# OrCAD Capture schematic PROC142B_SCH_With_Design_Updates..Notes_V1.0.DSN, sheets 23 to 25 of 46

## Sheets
23 22. OSPI INTERFACE: size C; title: SOC OSPI/QSPI INTERFACE AND OSPI FLASH
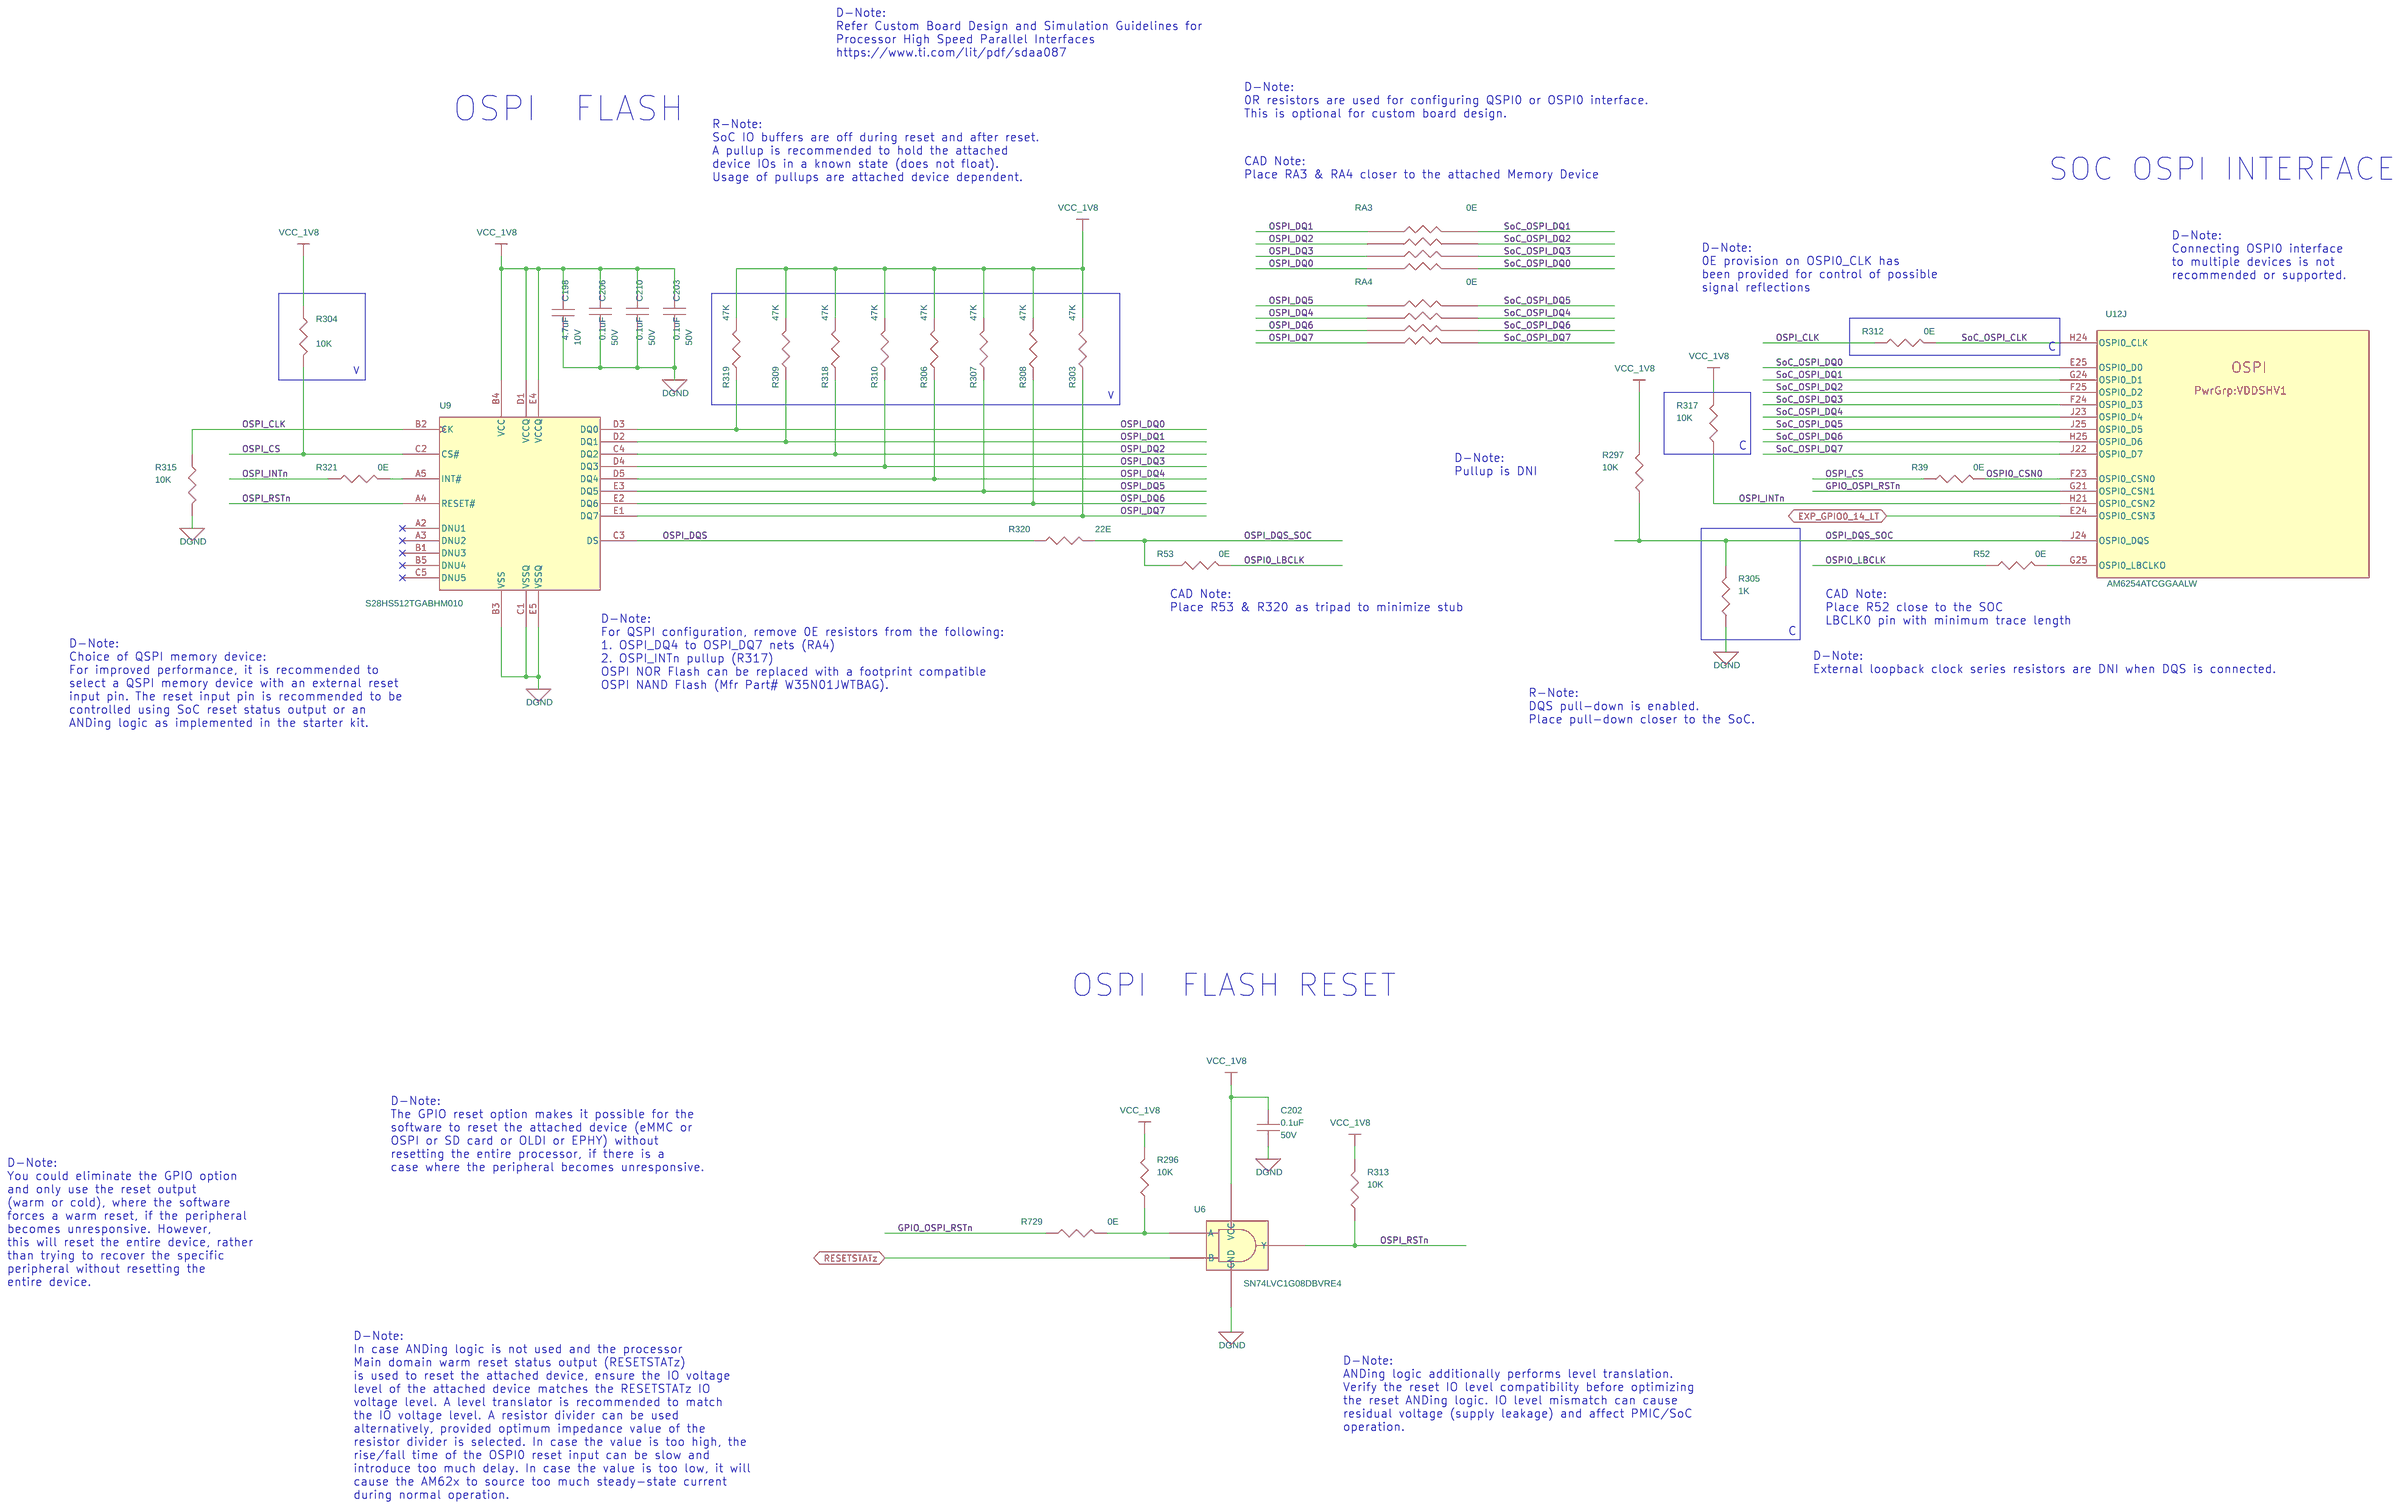
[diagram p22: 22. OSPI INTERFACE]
24 23. BRD ID EEPROM &TEMP SENSORS: size C; title: BOARD ID EEPROM & DIGITAL TEMPERATURE SENSORS
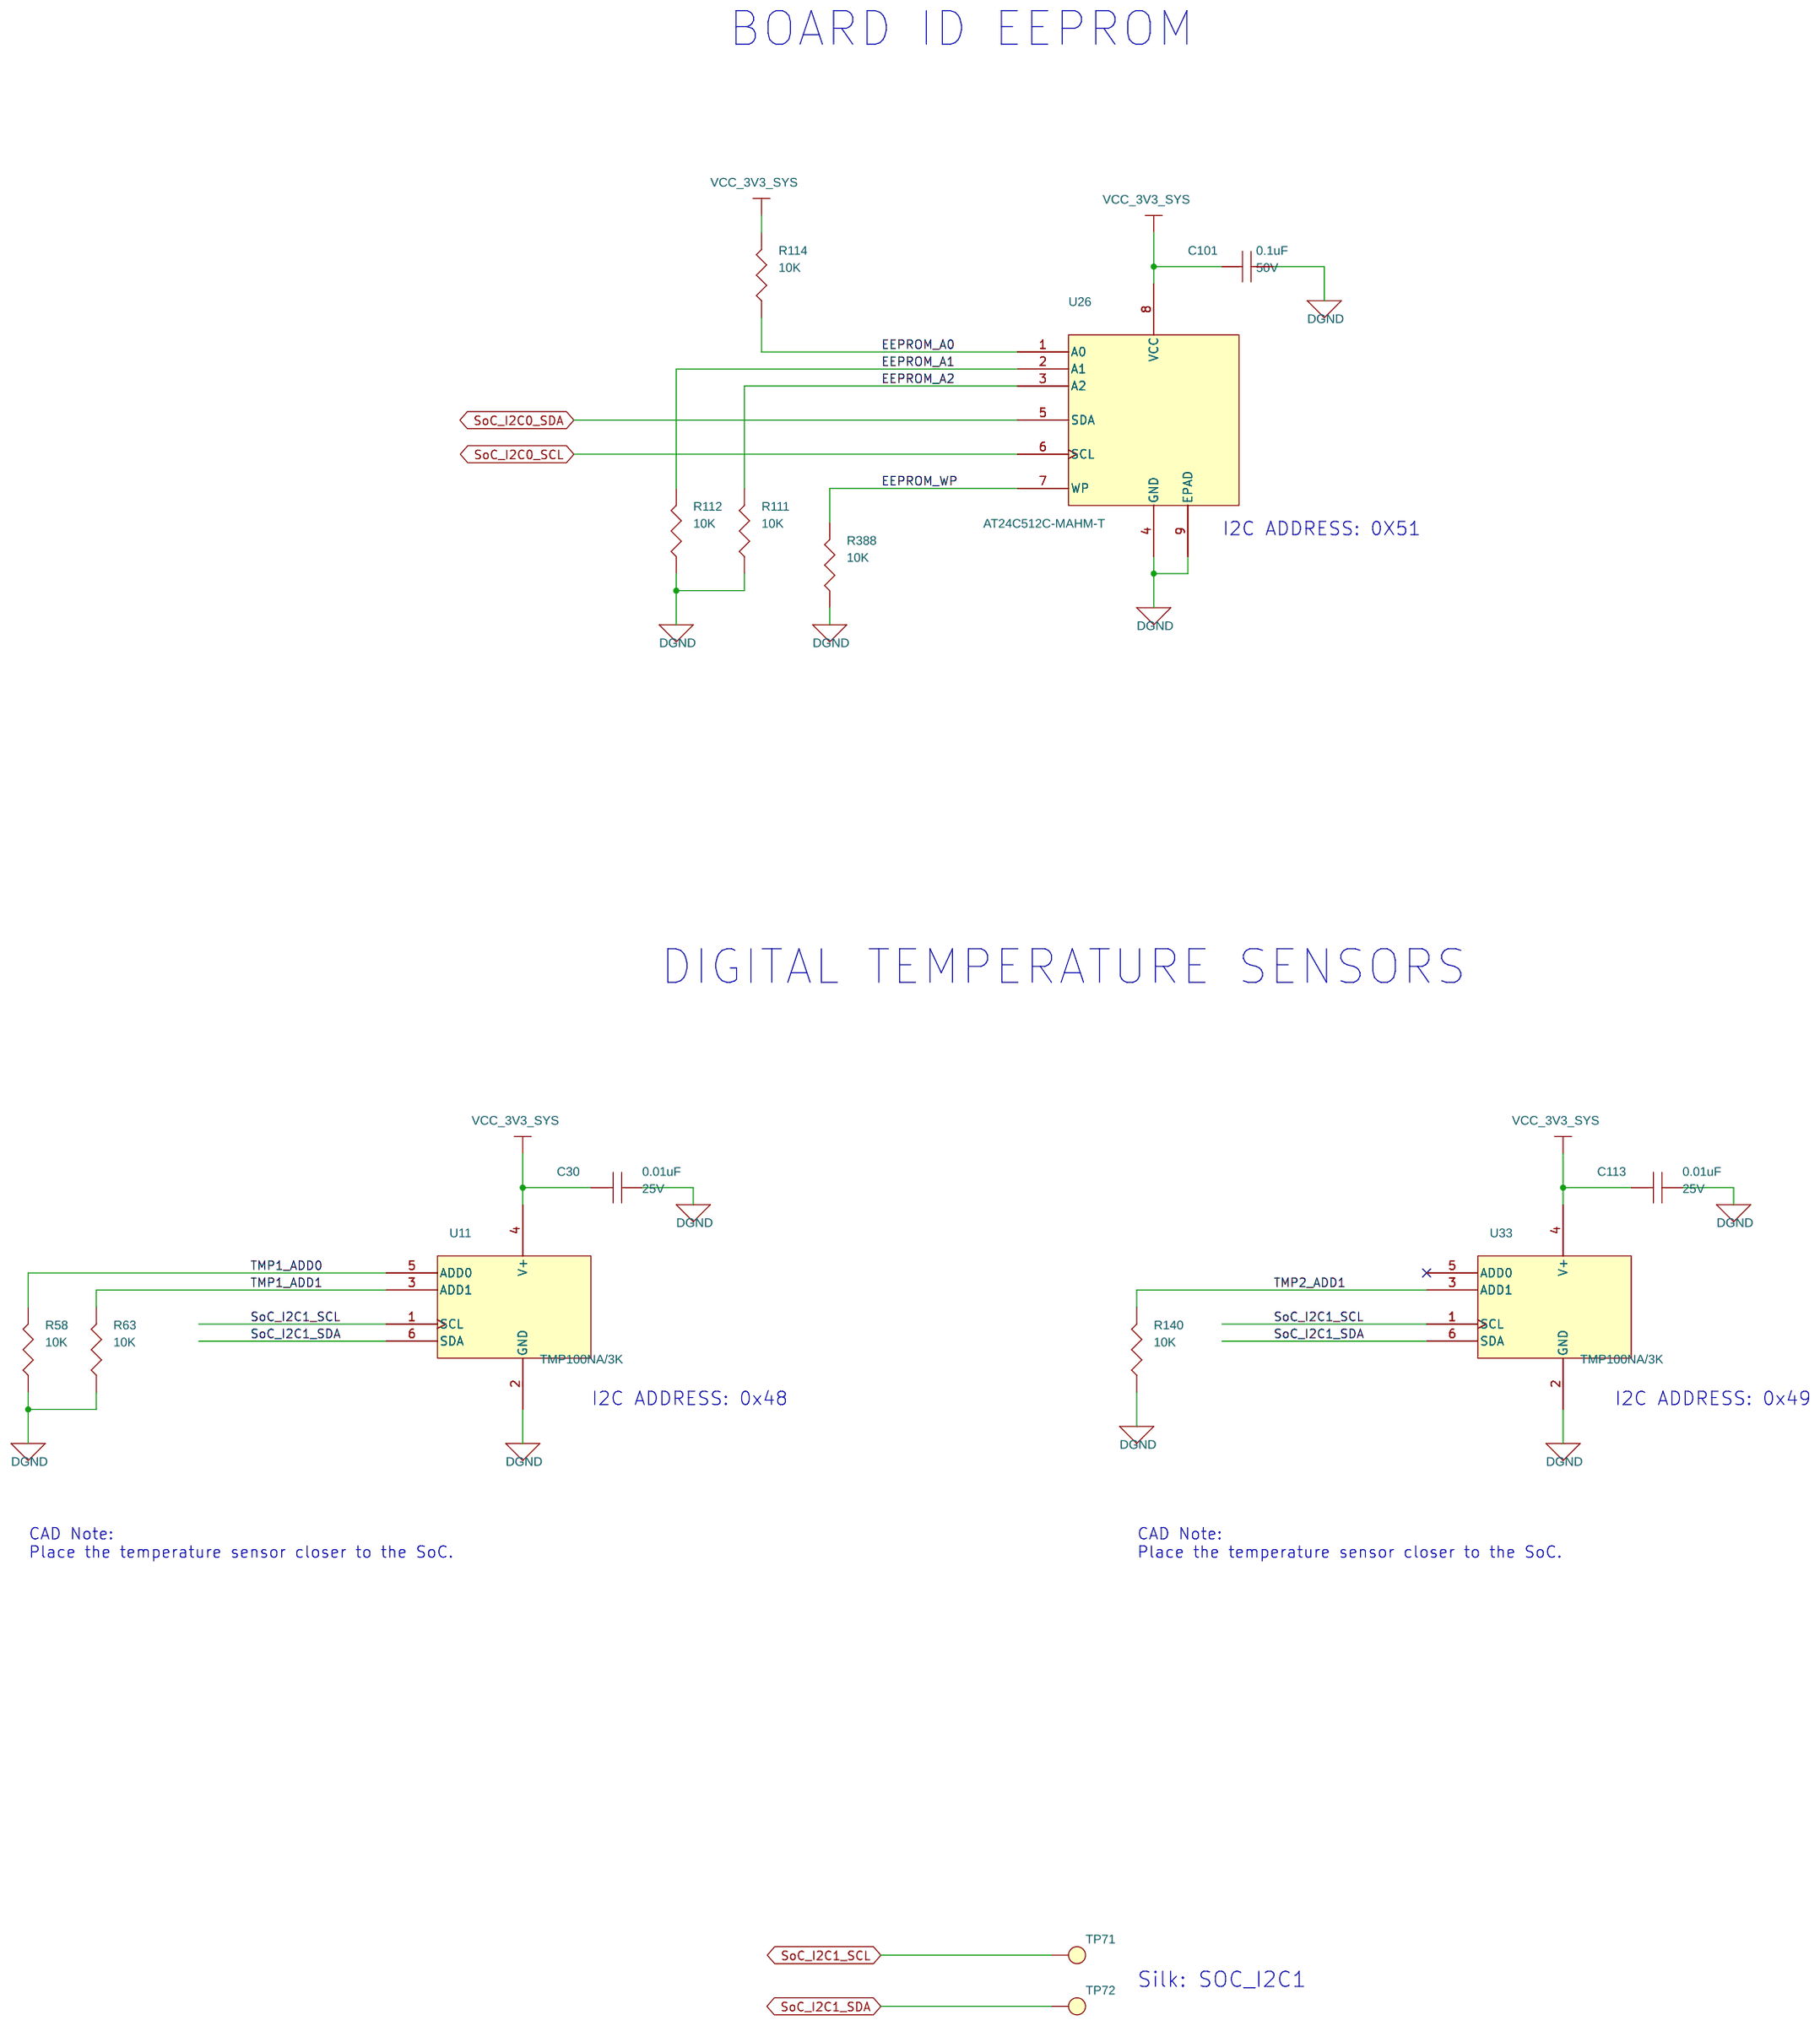
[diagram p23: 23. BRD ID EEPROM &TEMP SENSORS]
25 24. CPSW RGMII_1 ETHERNET PHY: size C; title: CPSW3G RGMII_1 ETHERNET PHY
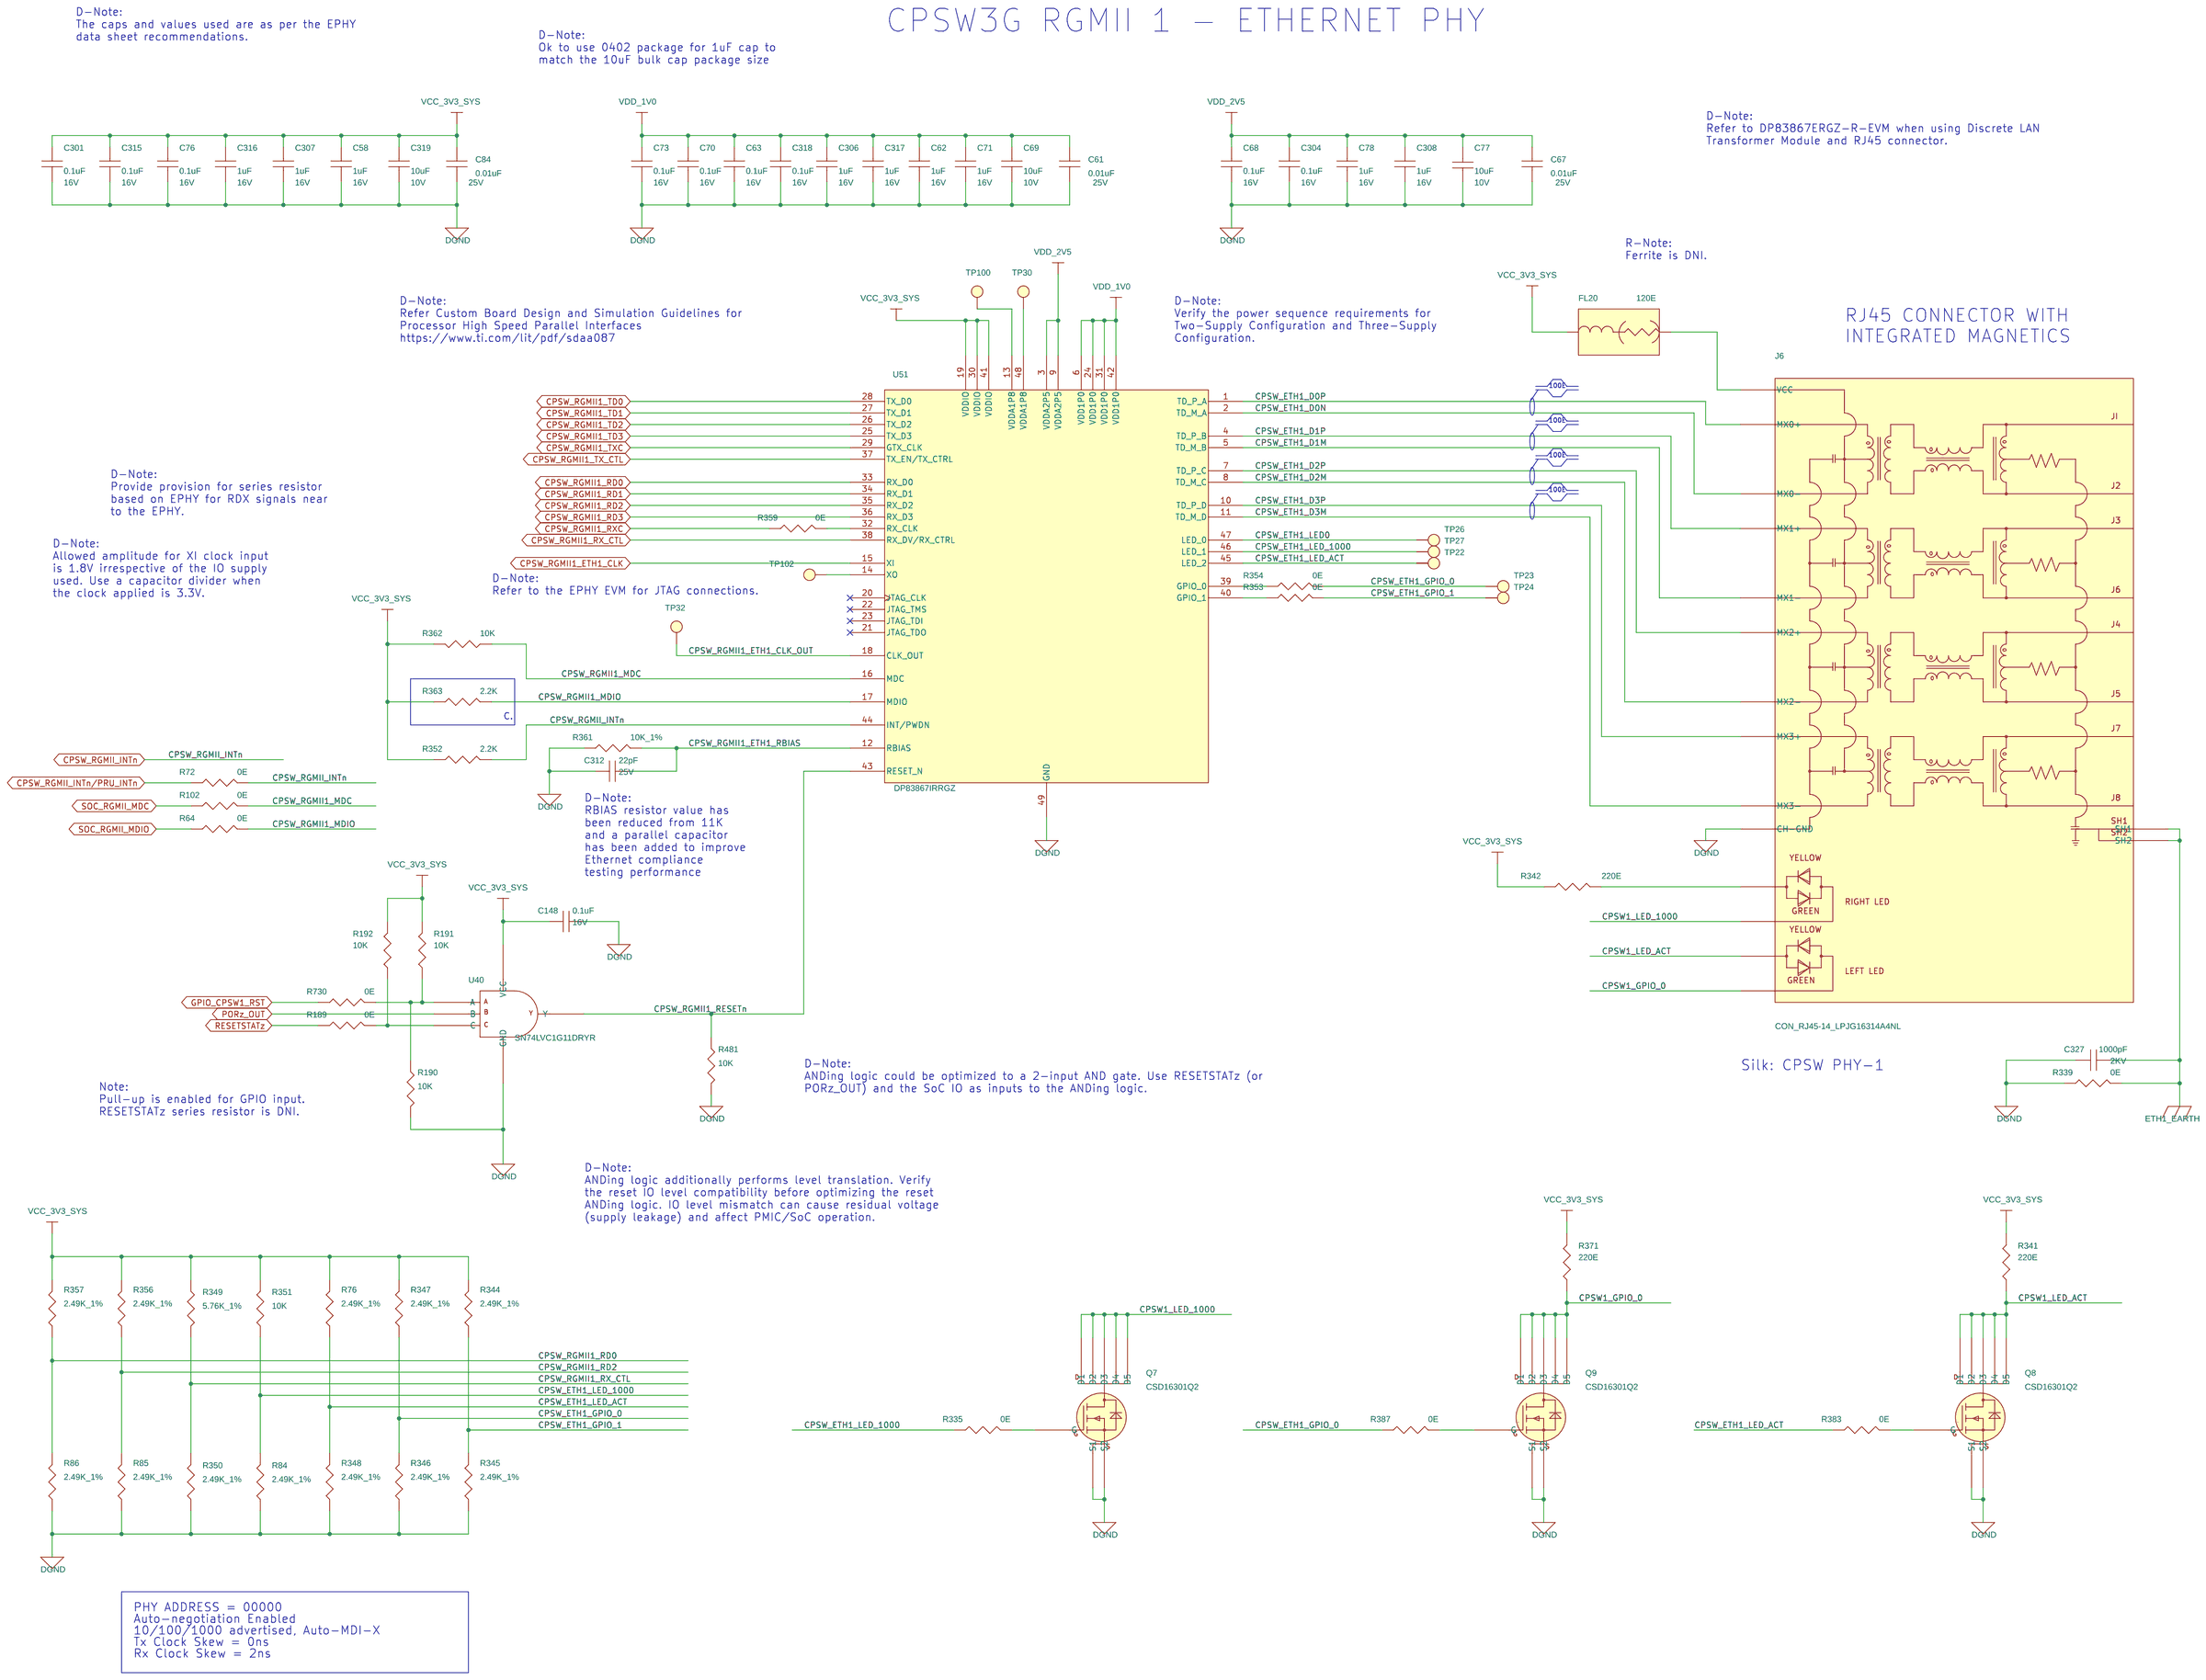
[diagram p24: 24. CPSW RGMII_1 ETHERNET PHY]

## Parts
sheet 22. OSPI INTERFACE
C198  4.7uF  [CAP0402_0-75]
C202  0.1uF  [CAP0402_0-75]
C203  0.1uF  [CAP0402_0-75]
C206  0.1uF  [CAP0402_0-75]
C210  0.1uF  [CAP0402_0-75]
R39  0E  [RES0201_0-5]
R52  0E  [RES0201_0-5]
R53  0E  [RES0402_0-5]
R296  10K  [RES0201_0-5]
R297  10K  [RES0201_0-5]
R303  47K  [RES0201_0-5]
R304  10K  [RES0402_0-5]
R305  1K  [RES0402_0-5]
R306  47K  [RES0201_0-5]
R307  47K  [RES0201_0-5]
R308  47K  [RES0201_0-5]
R309  47K  [RES0201_0-5]
R310  47K  [RES0201_0-5]
R312  0E  [RES0402_0-5]
R313  10K  [RES0201_0-5]
R315  10K  [RES0201_0-5]
R317  10K  [RES0201_0-5]
R318  47K  [RES0201_0-5]
R319  47K  [RES0201_0-5]
R320  22E  [RES0402_0-5]
R321  0E  [RES0402_0-5]
R729  0E  [RES0402_0-5]
RA3  0E  [RESA_EXB_0201-4_0-5]
RA4  0E  [RESA_EXB_0201-4_0-5]
U6  SN74LVC1G08DBVRE4  [SOT23-5]
U9  S28HS512TGABHM010  [BGA24_39-37_240X310_1]
sheet 23. BRD ID EEPROM &TEMP SENSORS
C30  0.01uF  [CAP0201_0-5]
C101  0.1uF  [CAP0402_0-75]
C113  0.01uF  [CAP0201_0-5]
R58  10K  [RES0201_0-5]
R63  10K  [RES0201_0-5]
R111  10K  [RES0201_0-5]
R112  10K  [RES0201_0-5]
R114  10K  [RES0201_0-5]
R140  10K  [RES0201_0-5]
R388  10K  [RES0201_0-5]
TP71  THRU HOLE  [TP_36X22]
TP72  THRU HOLE  [TP_36X22]
U11  TMP100NA/3K  [SOT23-6_1-5]
U26  AT24C512C-MAHM-T  [UDFN8_19-68_120X80_0-6]
U33  TMP100NA/3K  [SOT23-6_1-5]
sheet 24. CPSW RGMII_1 ETHERNET PHY
C58  1uF  [CAP0201_0-5]
C61  0.01uF  [CAP0201_0-5]
C62  1uF  [CAP0201_0-5]
C63  0.1uF  [CAP0201_0-5]
C67  0.01uF  [CAP0201_0-5]
C68  0.1uF  [CAP0201_0-5]
C69  10uF  [CAP0402_0-75]
C70  0.1uF  [CAP0201_0-5]
C71  1uF  [CAP0201_0-5]
C73  0.1uF  [CAP0201_0-5]
C76  0.1uF  [CAP0201_0-5]
C77  10uF  [CAP0402_0-75]
C78  1uF  [CAP0201_0-5]
C84  0.01uF  [CAP0201_0-5]
C148  0.1uF  [CAP0201_0-5]
C301  0.1uF  [CAP0201_0-5]
C304  0.1uF  [CAP0201_0-5]
C306  1uF  [CAP0201_0-5]
C307  1uF  [CAP0201_0-5]
C308  1uF  [CAP0201_0-5]
C312  22pF  [CAP0201_0-5]
C315  0.1uF  [CAP0201_0-5]
C316  1uF  [CAP0201_0-5]
C317  1uF  [CAP0201_0-5]
C318  0.1uF  [CAP0201_0-5]
C319  10uF  [CAP0402_0-75]
C327  1000pF  [CAP1206_1-75]
FL20  120E  [EMIFIL_BLM15P_0402]
J6  CON_RJ45-14_LPJG16314A4NL  [CON_RJ45-14_LPJG16314A4NL_S_R_T_13-6]
Q7  CSD16301Q2  [WSON6_CSD13202Q2_80X80_0-8]
Q8  CSD16301Q2  [WSON6_CSD13202Q2_80X80_0-8]
Q9  CSD16301Q2  [WSON6_CSD13202Q2_80X80_0-8]
R64  0E  [RES0402_0-5]
R72  0E  [RES0402_0-5]
R76  2.49K_1%  [RES0402_0-5]
R84  2.49K_1%  [RES0402_0-5]
R85  2.49K_1%  [RES0402_0-5]
R86  2.49K_1%  [RES0402_0-5]
R102  0E  [RES0402_0-5]
R189  0E  [RES0402_0-5]
R190  10K  [RES0201_0-5]
R191  10K  [RES0201_0-5]
R192  10K  [RES0201_0-5]
R335  0E  [RES0402_0-5]
R339  0E  [RES0603_0-75]
R341  220E  [RES0402_0-5]
R342  220E  [RES0402_0-5]
R344  2.49K_1%  [RES0402_0-5]
R345  2.49K_1%  [RES0402_0-5]
R346  2.49K_1%  [RES0402_0-5]
R347  2.49K_1%  [RES0402_0-5]
R348  2.49K_1%  [RES0402_0-5]
R349  5.76K_1%  [RES0402_0-5]
R350  2.49K_1%  [RES0402_0-5]
R351  10K  [RES0201_0-5]
R352  2.2K  [RES0402_0-5]
R353  0E  [RES0201_0-5]
R354  0E  [RES0201_0-5]
R356  2.49K_1%  [RES0402_0-5]
R357  2.49K_1%  [RES0402_0-5]
R359  0E  [RES0402_0-5]
R361  10K_1%  [RES0201_0-5]
R362  10K  [RES0201_0-5]
R363  2.2K  [RES0201_0-5]
R371  220E  [RES0402_0-5]
R383  0E  [RES0402_0-5]
R387  0E  [RES0402_0-5]
R481  10K  [RES0201_0-5]
R730  0E  [RES0402_0-5]
TP22  TP20_SMD  [TP20_SMD]
TP23  TP20_SMD  [TP20_SMD]
TP24  TP20_SMD  [TP20_SMD]
TP26  TP20_SMD  [TP20_SMD]
TP27  TP20_SMD  [TP20_SMD]
TP30  TP20_SMD  [TP20_SMD]
TP32  TP20_SMD  [TP20_SMD]
TP100  TP20_SMD  [TP20_SMD]
TP102  TP20_SMD  [TP20_SMD]
U40  SN74LVC1G11DRYR  [SON6_SN74LVC2G17_40X60_0-6]
U51  DP83867IRRGZ  [QFN48_19-68_280X280_1]
sheet 43. HDMI INTERFACE
U12  AM6254ATCGGAALW  [BGA425_19-68_510X510_0-7]  (sections A,B,C,D,E,F,G,H,I,J,K,L,M,N,O,P,Q,R)

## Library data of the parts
C198 = CAP: CAP CERAMIC 4.7uF 10V 20% X5R 0402; Chkd/date: MANIRAJA/110718; Crtd /date: ALVY/110718; Custom_Duty: 15%; Customs_HS_Code: 85322990; Distributor_name: DIGIKEY; Distributor_part_number: 490-14306-1-ND; Footprint Path: Y:\MIS_DATABASE\Library\ALTIUM_TOOL\PCB_FOOTPRINTS\Altium_Footprint_Lib.PcbLib; Height: 0.65MM; Library Path: Y:\MIS_DATABASE\Library\ALTIUM_TOOL\SCHEMATICS_PARTS\MS_DISCRETE_Library.schlib; Mfr_name: MURATA; Mfr_part_number: GRM155R61A475MEAAD; Mistral Part No: 120012060002-R; Package: 0402; Part_type: CAPACITORS\CERAMIC; Project: TI_J7SVB_PCIE_ADD-ON-CARD; RoHS: RoHS; Temperature: -55°C+85°C; Tolerance: 20%; Voltage: 10V; Wattage: NA; Weight: 14mg; Datasheet: Y:\MIS_DATABASE\DATASHEETS\CAPACITORS\GRM155R61A475MEAAD.PDF
C101 C202 C203 C206 C210 = CAP: CAP CERAMIC 0.1uF 50V 10% X7R 0402; Alt_Mfr_name: YAGEO AMERICA; Alt_Mfr_part_number: CC0402KRX5R8BB104; Chkd/date: MANIRAJA/261020; Crtd /date: ALVY/211020; Custom_Duty: 15%; Customs_HS_Code: 85322990; Distributor_name: DIGIKEY; Distributor_part_number: 490-10700-1-ND; Footprint Path: Y:\MIS_DATABASE\Library\ALTIUM_TOOL\PCB_FOOTPRINTS\Altium_Footprint_Lib.PcbLib; Height: 0.55MM; Library Path: Y:\MIS_DATABASE\Library\ALTIUM_TOOL\SCHEMATICS_PARTS\MS_DISCRETE_Library.schlib; Mfr_name: MURATA; Mfr_part_number: GRM155R71H104KE14D; Mistral Part No: 120011100014-R; Package: 0402; Part_type: CAPACITORS\CERAMIC; Project: J7_CP; RoHS: RoHS; Temperature: -55°C+125°C; Tolerance: 10%; Voltage: 50V; Wattage: NA; Weight: 3.1mg; Datasheet: Y:\MIS_DATABASE\DATASHEETS\CAPACITORS\GRM155R71H104KE14.PDF
R39 R52 = RESISTOR: RES 0E 1/20W 5% 0201; Chkd/date: NAVEED/301214; Crtd /date: MUDDU/120710; Custom_Duty: 15%; Customs_HS_Code: 85332119; Distributor_name: DIGIKEY; Distributor_part_number: 311-0.0NCT-ND; Footprint Path: Y:\MIS_DATABASE\Library\ALTIUM_TOOL\PCB_FOOTPRINTS\Altium_Footprint_Lib.PcbLib; Height: 0.26MM; Library Path: Y:\MIS_DATABASE\Library\ALTIUM_TOOL\SCHEMATICS_PARTS\MS_DISCRETE_Library.schlib; Mfr_name: YAGEO AMERICA; Mfr_part_number: RC0201JR-070RL; Mistral Part No: 110010070067-R; Package: 0201; Part_type: RESISTORS\FIXED; Project: PB_BUGBASE; RoHS: RoHS; SIGNAL_MODEL: RESISTOR_RES0201_0-5_0E_0E; Temperature: -55°C+125°C; Tolerance: 5%; Voltage: NA; Wattage: 1/20W; Weight: 0.17mg; Datasheet: Y:\MIS_DATABASE\DATASHEETS\RESISTORS\RCXXXXL-SER_MAR18.PDF
R53 R64 R72 R102 R189 R321 R335 R383 R387 R729 R730 = RESISTOR: RES 0E 1/16W JUMPER 0402; Chkd/date: VASANTHA/201216; Crtd /date: MUDDU/190810; Custom_Duty: 15%; Customs_HS_Code: 85332119; Distributor_name: DIGIKEY; Distributor_part_number: 541-0.0JCT-ND; Footprint Path: Y:\MIS_DATABASE\Library\ALTIUM_TOOL\PCB_FOOTPRINTS\Altium_Footprint_Lib.PcbLib; Height: 0.40MM; Library Path: Y:\MIS_DATABASE\Library\ALTIUM_TOOL\SCHEMATICS_PARTS\MS_DISCRETE_Library.schlib; Mfr_name: VISHAY; Mfr_part_number: CRCW04020000Z0ED; Mistral Part No: 110010080019-R; Package: 0402; Part_type: RESISTORS\FIXED; Project: PB_BUGBASE; RoHS: RoHS; Temperature: -55°C+155°C; Tolerance: NA; Voltage: NA; Wattage: 1/16W; Weight: 0.65mg; Datasheet: Y:\MIS_DATABASE\DATASHEETS\RESISTORS\CRCW0603.PDF
R58 R63 R111 R112 R114 R140 R190-R192 R296 R297 R313 R315 R317 R351 R362 R388 R481 = RESISTOR: RES 10K 1/20W 5% 0201; Chkd/date: MANIRAJA/050517; Crtd /date: MANIRAJA/050517; Custom_Duty: 15%; Customs_HS_Code: 85332119; Distributor_name: DIGIKEY; Distributor_part_number: 311-10KNCT-ND; Footprint Path: Y:\MIS_DATABASE\Library\ALTIUM_TOOL\PCB_FOOTPRINTS\Altium_Footprint_Lib.PcbLib; Height: 0.26MM; Library Path: Y:\MIS_DATABASE\Library\ALTIUM_TOOL\SCHEMATICS_PARTS\MS_DISCRETE_Library.schlib; Mfr_name: YAGEO AMERICA; Mfr_part_number: RC0201JR-0710KL; Mistral Part No: 110010070051-R; Package: 0201; Part_type: RESISTORS\FIXED; Project: GOLDEN-I LITE; RoHS: RoHS; Temperature: -55°C+125°C; Tolerance: 5%; Voltage: NA; Wattage: 1/20W; Weight: 0.17mg; Datasheet: Y:\MIS_DATABASE\DATASHEETS\RESISTORS\RCXXXXL-SER_MAR18.PDF
R303 R306-R310 R318 R319 = RESISTOR: RES 47K 1/20W 5% 0201; Chkd/date: PRADEEP/280823; Crtd /date: SHANKARI/280824; Custom_Duty: 15%; Customs_HS_Code: 85332119; Distributor_name: DIGIKEY; Distributor_part_number: P123333CT-ND; Footprint Path: Y:\MIS_DATABASE\Library\ALTIUM_TOOL\PCB_FOOTPRINTS\Altium_Footprint_Lib.PcbLib; Height: 0.26MM; Library Path: Y:\MIS_DATABASE\Library\ALTIUM_TOOL\SCHEMATICS_PARTS\MS_DISCRETE_Library.schlib; Mfr_name: PANASONIC-ECG; Mfr_part_number: ERJ-1GNJ473C; Mistral Part No: 110024080020-R; Package: 0201; Part_type: RESISTORS\FIXED; Project: AM26L_EVM; RoHS: RoHS; Temperature: -55°C+125°C; Tolerance: 5%; Voltage: NA; Wattage: 1/20W; Weight: NA; Datasheet: Y:\MIS_DATABASE\DATASHEETS\RESISTORS\ERJ-1GNJ473C.PDF
R304 = RESISTOR: RES 10K 1/16W 5% 0402; Chkd/date: MANIRAJA/120219; Crtd /date: MANIRAJA/120219; Custom_Duty: 15%; Customs_HS_Code: 85332119; Distributor_name: DIGIKEY; Distributor_part_number: 541-10KJCT-ND; Footprint Path: Y:\MIS_DATABASE\Library\ALTIUM_TOOL\PCB_FOOTPRINTS\Altium_Footprint_Lib.PcbLib; Height: 0.40MM; Library Path: Y:\MIS_DATABASE\Library\ALTIUM_TOOL\SCHEMATICS_PARTS\MS_DISCRETE_Library.schlib; Mfr_name: VISHAY; Mfr_part_number: CRCW040210K0JNED; Mistral Part No: 110011060021-R; Package: 0402; Part_type: RESISTORS\FIXED; Project: NEXTNAV_ORBIT_MODULE; RoHS: RoHS; Temperature: -55°C+155°C; Tolerance: 5%; Voltage: NA; Wattage: 1/16W; Weight: 0.65mg; Datasheet: Y:\MIS_DATABASE\DATASHEETS\RESISTORS\CRCW0603.PDF
R305 = RESISTOR: RES 1K 1/10W 5% 0402; Chkd/date: VASANTHA/201216; Crtd /date: MAZHAR/230805; Custom_Duty: 15%; Customs_HS_Code: 85332119; Distributor_name: DIGIKEY; Distributor_part_number: P1.0KJCT-ND; Footprint Path: Y:\MIS_DATABASE\Library\ALTIUM_TOOL\PCB_FOOTPRINTS\Altium_Footprint_Lib.PcbLib; Height: 0.40MM; Library Path: Y:\MIS_DATABASE\Library\ALTIUM_TOOL\SCHEMATICS_PARTS\MS_DISCRETE_Library.schlib; Mfr_name: PANASONIC-ECG; Mfr_part_number: ERJ-2GEJ102X; Mistral Part No: 110009030400-R; Package: 0402; Part_type: RESISTORS\FIXED; Project: HSE; RoHS: RoHS; Temperature: -55°C+155°C; Tolerance: 5%; Voltage: NA; Wattage: 1/10W; Weight: 0.8mg; Datasheet: Y:\MIS_DATABASE\DATASHEETS\RESISTORS\PAN-ERJSER_NOV17.PDF
R312 R359 = RESISTOR: RES 0E 1/16W JUMPER 0402; Chkd/date: VASANTHA/201216; Crtd /date: MUDDU/190810; Custom_Duty: 15%; Customs_HS_Code: 85332119; Distributor_name: DIGIKEY; Distributor_part_number: 541-0.0JCT-ND; Footprint Path: Y:\MIS_DATABASE\Library\ALTIUM_TOOL\PCB_FOOTPRINTS\Altium_Footprint_Lib.PcbLib; Height: 0.40MM; Library Path: Y:\MIS_DATABASE\Library\ALTIUM_TOOL\SCHEMATICS_PARTS\MS_DISCRETE_Library.schlib; Mfr_name: VISHAY; Mfr_part_number: CRCW04020000Z0ED; Mistral Part No: 110010080019-R; Package: 0402; Part_type: RESISTORS\FIXED; Project: PB_BUGBASE; RoHS: RoHS; SIGNAL_MODEL: RESISTOR_RES0402_0-5_0E_0E; Temperature: -55°C+155°C; Tolerance: NA; Voltage: NA; Wattage: 1/16W; Weight: 0.65mg; Datasheet: Y:\MIS_DATABASE\DATASHEETS\RESISTORS\CRCW0603.PDF
R320 = RESISTOR: RES 22E 1/16W 5% 0402; Chkd/date: ALVY/210122; Crtd /date: TAMILARASU/210122; Custom_Duty: 15%; Customs_HS_Code: 85332119; Distributor_name: DIGIKEY; Distributor_part_number: 311-22JRCT-ND; Footprint Path: Y:\MIS_DATABASE\Library\ALTIUM_TOOL\PCB_FOOTPRINTS\Altium_Footprint_Lib.PcbLib; Height: 0.40MM; Library Path: Y:\MIS_DATABASE\Library\ALTIUM_TOOL\SCHEMATICS_PARTS\MS_DISCRETE_Library.schlib; Manufacturer: YAGEO; Mfr_name: YAGEO AMERICA; Mfr_part_number: RC0402JR-0722RL; Mistral Part No: 110022010018-R; Package: 0402; Part_type: RESISTORS\FIXED; Project: DLRL DIGITAL RECEIVER_BRD; RoHS: RoHS; Temperature: -55°C+155°C; Tolerance: 5%; Voltage: NA; Wattage: 1/16W; Weight: 0.65mg; Datasheet: Y:\MIS_DATABASE\DATASHEETS\RESISTORS\RCXXXXP-SER_SEP18.PDF
RA3 RA4 = RESARR_ISO4: RES ARRAY 0E 31mW JUMPER 0201-4; Chkd/date: MANIRAJA/290918; Crtd /date: MANIRAJA/290918; Custom_Duty: 15%; Customs_HS_Code: 85332119; Distributor_name: DIGIKEY; Distributor_part_number: Y6000CT-ND; Footprint Path: Y:\MIS_DATABASE\Library\ALTIUM_TOOL\PCB_FOOTPRINTS\Altium_Footprint_Lib.PcbLib; Height: 0.45MM; Library Path: Y:\MIS_DATABASE\Library\ALTIUM_TOOL\SCHEMATICS_PARTS\MS_DISCRETE_Library.schlib; Manufacturer: PANASONIC-ECG; Mfr_part_number: EXB-18VR000X; Mistral Part No: 110018090033-R; Package: 0201-4; Part_type: RESISTORS\ARRAY; Project: TI_60GHz-AOP; RoHS: RoHS; Temperature: -55°C+125°C; Tolerance: NA; Voltage: NA; Wattage: 31mW; Weight: 1mg; Datasheet: Y:\MIS_DATABASE\DATASHEETS\RESISTORS\EXB-18V.PDF
U6 = SN74LVC1G08DBVRE4_SOT23-5: IC SINGLE 2-INPUT POSITIVE AND GATE SOT23-5; Chkd/date: SUHAS/221010; Crtd /date: USMAN/151008; Custom_Duty: 15%; Customs_HS_Code: 85423100; Distributor_name: DIGIKEY; Distributor_part_number: SN74LVC1G08DBVRE4-ND; Height: 1.45MM; Mfr_name: TEXAS INSTRUMENTS; Mistral Part No: 141009060026-R; Part_type: ICS\DIGITAL\GATES; Project: KHAN_MAIN; RoHS: Sb/ Br FREE; Temperature: -40°C+85°C; Datasheet: Y:\MIS_DATABASE\DATASHEETS\ICS\DIGITAL\GATES\SN74LVC1G08.PDF
U9 = S28HS512T_BGA24: IC 1.8V 512Mb SEMPER FLASH WITH OCTAL INTERFACE BGA24; Chkd/date: MANIRAJA/170120; Crtd /date: ALVY/170120; Custom_Duty: 15%; Customs_HS_Code: 85423100; Distributor_name: NA; Distributor_part_number: NA; Footprint Path: Y:\MIS_DATABASE\Library\ALTIUM_TOOL\PCB_FOOTPRINTS\Altium_Footprint_Lib.PcbLib; Height: 1.00MM; Library Path: Y:\MIS_DATABASE\Library\ALTIUM_TOOL\SCHEMATICS_PARTS\MS_MISCMEMORY_Library.schlib; Mfr_name: CYPRESS SEMICONDUCTOR; Mistral Part No: 141120010002; Package: BGA24; Part_type: ICS\DIGITAL\MEMORY; Project: J7VCL_SOM DUAL LEO PMIC; RoHS: NA; Temperature: -40°C+125°C; Tolerance: NA; Voltage: NA; Wattage: NA; Weight: NA; Datasheet: Y:\MIS_DATABASE\DATASHEETS\ICS\MEMORY\S28HS512T.PDF
C30 C61 C67 C84 C113 = CAP: CAP CERAMIC 0.01uF 25V 10% X5R 0201; Chkd/date: MANIRAJA/230118; Crtd /date: MANIRAJA/230118; Custom_Duty: 15%; Customs_HS_Code: 85322990; Distributor_name: DIGIKEY; Distributor_part_number: GRM033R61E103KA12J-ND; Footprint Path: Y:\MIS_DATABASE\Library\ALTIUM_TOOL\PCB_FOOTPRINTS\Altium_Footprint_Lib.PcbLib; Height: 0.33MM; Library Path: Y:\MIS_DATABASE\Library\ALTIUM_TOOL\SCHEMATICS_PARTS\MS_DISCRETE_Library.schlib; Mfr_name: MURATA; Mfr_part_number: GRM033R61E103KA12J; Mistral Part No: 120018010007-R; Package: 0201; Part_type: CAPACITORS\CERAMIC; Project: TI_MAXIE_CPB; RoHS: RoHS; Temperature: -55°C+85°C; Tolerance: 10%; Voltage: 25V; Wattage: NA; Weight: 0.33mg; Datasheet: Y:\MIS_DATABASE\DATASHEETS\CAPACITORS\GRM033R61E103KA12.PDF
TP71 TP72 = TESTPOINT: TESTPOINT 0.56MM DRILL PTH; Chkd/date: BAVISH/040311; Crtd /date: MAZHAR/110405; Distributor_name: NA; Distributor_part_number: NA; Height: NA; Mfr_name: LOCAL; Mistral Part No: 130010010008; Package: THRU-HOLE; Project: KOPIN_MODULS; Temperature: NA; Tolerance: NA; Voltage: NA; Wattage: NA; Weight: NA; Datasheet: NA
U11 U33 = TMP100NA_3K_SOT23-6: IC TEMPERATURE SENSOR WITH I2C AND SMBUS INTERFACE SOT23-6; Chkd/date: MANIRAJA/290817; Crtd /date: MANIRAJA/290817; Custom_Duty: 15%; Customs_HS_Code: 85423100; Distributor_name: DIGIKEY; Distributor_part_number: 296-26833-1-ND; Height: 1.45MM; Library Ref: TMP100NA/3K_SOT23-6; Mfr_name: TEXAS INSTRUMENTS; Mistral Part No: 141017080030-R; Package: SOT23-6; Part_type: ICS\DIGITAL\PERIPHERAL; Project: TI_MAXIE_CPB; RoHS: RoHS; Temperature: -55°C+125°C; Tolerance: NA; Voltage: NA; Wattage: NA; Weight: 120mg; Datasheet: Y:\MIS_DATABASE\DATASHEETS\ICS\DIGITAL\PERIPHERAL\TMP10XX.PDF
U26 = AT24C64D-MAHM-T_UDFN8: IC 1.7-3.6V 512Kb I2C COMPATIBLE SERIAL EEPROM UDFN8; Chkd/date: MANIRAJA/240919; Crtd /date: ALVY/240919; Custom_Duty: 15%; Customs_HS_Code: 85423100; Distributor_name: DIGIKEY; Distributor_part_number: AT24C512C-MAHM-TCT-ND; Footprint Path: Y:\MIS_DATABASE\Library\ALTIUM_TOOL\PCB_FOOTPRINTS\Altium_Footprint_Lib.PcbLib; Height: 0.60MM; Library Path: Y:\MIS_DATABASE\Library\ALTIUM_TOOL\SCHEMATICS_PARTS\MS_MISCMEMORY_Library.schlib; Mfr_name: MICROCHIP; Mistral Part No: 141119090004-R; Package: UDFN8; Part_type: ICS\DIGITAL\MEMORY; Project: HAL_3U-T1042-SBC; RoHS: RoHS; Temperature: -40°C+85°C; Tolerance: NA; Voltage: NA; Wattage: NA; Weight: 9.5mg; Datasheet: Y:\MIS_DATABASE\DATASHEETS\ICS\MEMORY\AT24C512C.PDF
C58 C62 C71 C78 C306-C308 C316 C317 = CAP: CAP CERAMIC 1uF 16V 20% X5R 0201; Chkd/date: MANIRAJA/300520; Crtd /date: ALVY/260520; Custom_Duty: 15%; Customs_HS_Code: 85322990; Distributor_name: DIGIKEY; Distributor_part_number: 490-18654-1-ND; Footprint Path: Y:\MIS_DATABASE\Library\ALTIUM_TOOL\PCB_FOOTPRINTS\Altium_Footprint_Lib.PcbLib; Height: 0.39MM; Library Path: Y:\MIS_DATABASE\Library\ALTIUM_TOOL\SCHEMATICS_PARTS\MS_DISCRETE_Library.schlib; Mfr_name: MURATA; Mfr_part_number: GRM033R61C105ME15D; Mistral Part No: 120018090038-R; Package: 0201; Part_type: CAPACITORS\CERAMIC; Project: QCS610_NANOSOM; RoHS: RoHS; Temperature: -55°C+85°C; Tolerance: 20%; Voltage: 16V; Wattage: NA; Weight: 0.33mg; Datasheet: Y:\MIS_DATABASE\DATASHEETS\CAPACITORS\GRM033R61C105ME15.PDF
C63 C68 C70 C73 C76 C148 C301 C304 C315 C318 = CAP: CAP CERAMIC 0.1uF 16V 10% X5R 0201; Alt_Mfr_name: YAGEO AMERICA; Alt_Mfr_part_number: CC0402KRX5R8BB104; Chkd/date: MANIRAJA/230118; Crtd /date: MANIRAJA/230118; Custom_Duty: 15%; Customs_HS_Code: 85322990; Distributor_name: DIGIKEY; Distributor_part_number: 490-14305-1-ND; Footprint Path: Y:\MIS_DATABASE\Library\ALTIUM_TOOL\PCB_FOOTPRINTS\Altium_Footprint_Lib.PcbLib; Height: 0.33MM; Library Path: Y:\MIS_DATABASE\Library\ALTIUM_TOOL\SCHEMATICS_PARTS\MS_DISCRETE_Library.schlib; Mfr_name: MURATA; Mfr_part_number: GRM033R61C104KE14D; Mistral Part No: 120009030072-R; Package: 0201; Part_type: CAPACITORS\CERAMIC; Project: TI_MAXIE_CPB; RoHS: RoHS; Temperature: -55°C+85°C; Tolerance: 10%; Voltage: 16V; Wattage: NA; Weight: 0.33mg; Datasheet: Y:\MIS_DATABASE\DATASHEETS\CAPACITORS\GRM033R61C104KE14.PDF
C69 C77 C319 = CAP: CAP CERAMIC 10uF 10V 20% X5R 0402; Chkd/date: MANIRAJA/300520; Crtd /date: ALVY/260520; Custom_Duty: 15%; Customs_HS_Code: 85322990; Distributor_name: DIGIKEY; Distributor_part_number: 490-GRM155R61A106ME11DTR-ND; Footprint Path: Y:\MIS_DATABASE\Library\ALTIUM_TOOL\PCB_FOOTPRINTS\Altium_Footprint_Lib.PcbLib; Height: 0.55MM; Library Path: Y:\MIS_DATABASE\Library\ALTIUM_TOOL\SCHEMATICS_PARTS\MS_DISCRETE_Library.schlib; Mfr_name: MURATA; Mfr_part_number: GRM155R61A106ME11D; Mistral Part No: 120013110019-R; Package: 0402; Part_type: CAPACITORS\CERAMIC; Project: QCS610_NANOSOM; RoHS: RoHS; Temperature: -55°C+85°C; Tolerance: 20%; Voltage: 10V; Wattage: NA; Weight: 3.1mg; Datasheet: Y:\MIS_DATABASE\DATASHEETS\CAPACITORS\MURATA-GXX-SER_NOV17.PDF
C312 = CAP: CAP CERAMIC 22pF 25V 1% C0G(NP0) 0201; Chkd/date: MANIRAJA/270721; Crtd /date: ALVY/260721; Custom_Duty: 15%; Customs_HS_Code: 85322990; Distributor_name: DIGIKEY; Distributor_part_number: 490-14545-1-ND; Footprint Path: Y:\MIS_DATABASE\Library\ALTIUM_TOOL\PCB_FOOTPRINTS\Altium_Footprint_Lib.PcbLib; Height: 0.33MM; Library Path: Y:\MIS_DATABASE\Library\ALTIUM_TOOL\SCHEMATICS_PARTS\MS_DISCRETE_Library.schlib; Mfr_name: MURATA; Mfr_part_number: GRM0335C1E220FA01D; Mistral Part No: 120021070019-R; Package: 0201; Part_type: CAPACITORS\CERAMIC; Project: TI_AM335x SK_BRD; RoHS: RoHS; Temperature: -55°C+125°C; Tolerance: 1%; Voltage: 25V; Wattage: NA; Weight: 0.33mg; Datasheet: Y:\MIS_DATABASE\DATASHEETS\CAPACITORS\GRM0335C1E220FA01.PDF
C327 = CAP: CAP CERAMIC 1000pF 2KV 10% X7R 1206; Chkd/date: SHREESHAIL/291106; Crtd /date: MAZHAR/281106; Custom_Duty: 15%; Customs_HS_Code: 85322990; Distributor_name: DIGIKEY; Distributor_part_number: 478-2956-1-ND; Footprint Path: Y:\MIS_DATABASE\Library\ALTIUM_TOOL\PCB_FOOTPRINTS\Altium_Footprint_Lib.PcbLib; Height: 1.52MM; Library Path: Y:\MIS_DATABASE\Library\ALTIUM_TOOL\SCHEMATICS_PARTS\MS_DISCRETE_Library.schlib; Mfr_name: AVX CORPORATION; Mfr_part_number: 1206GC102KAT1A; Mistral Part No: 120015080006-R; Package: 1206; Part_type: CAPACITORS\CERAMIC; Project: ADR1B; RoHS: RoHS; Temperature: -55°C+125°C; Tolerance: 10%; Voltage: 2KV; Wattage: NA; Weight: 16.2mg; Datasheet: Y:\MIS_DATABASE\DATASHEETS\CAPACITORS\AVX_HV-MLC.PDF
FL20 = EMIFILTER_IND: FERRITE CHIP 120E 2A 0402; Chkd/date: NAVEED/241114; Crtd /date: USMAN/170613; Custom_Duty: 24%; Customs_HS_Code: 85369090; Distributor_name: MOUSER; Distributor_part_number: 81-BLM15PX121SN1D; Height: 0.55MM; Mfr_name: MURATA; Mfr_part_number: BLM15PX121SN1D; Mistral Part No: 130013060022-R; Package: 0402; Part_type: FILTER; Project: GEN_3-8; RoHS: RoHS; Temperature: -55°C+125°C; Tolerance: 25%; Voltage: NA; Wattage: NA; Weight: NA; Datasheet: Y:\MIS_DATABASE\DATASHEETS\DISCRETES\INDUCTORS\BLM15X.PDF
J6 = CON_RJ45-14_LPJG16314A4NL: CON RJ-45 FEMALE 14POS RT TH; Chkd/date: VASANTHA/150714; Crtd /date: BALACHANDAR/120614; Custom_Duty: 24%; Customs_HS_Code: 85369090; Distributor_name: NA; Distributor_part_number: NA; Footprint Path: Y:\MIS_DATABASE\Library\ALTIUM_TOOL\PCB_FOOTPRINTS\Altium_Footprint_Lib.PcbLib; Height: 13.60MM; Library Path: Y:\MIS_DATABASE\Library\ALTIUM_TOOL\SCHEMATICS_PARTS\MS_CONNECTOR_Library.schlib; Mfr_name: LINK-PP; Mfr_part_number: LPJG16314A4NL; Mistral Part No: 150014060029-R; Package: THRU-HOLE; Part_type: CONNECTOR\JACK; Project: AEGIS; RoHS: RoHS; Temperature: -0°C+70°C; Tolerance: NA; Voltage: NA; Wattage: NA; Weight: NA; Datasheet: Y:\MIS_DATABASE\DATASHEETS\CONNECTORS\LPJG16314A4NL.PDF
Q7-Q9 = MOSFET_CSD17313Q2: IC MOSFET N-CHANNEL NEXFET 25V WSON6; Chkd/date: ALVY/071220; Crtd /date: MANIRAJA/071220; Custom_Duty: 15%; Customs_HS_Code: 85423100; Distributor_name: DIGIKEY; Distributor_part_number: 296-25260-1-ND; Footprint Path: Y:\MIS_DATABASE\Library\ALTIUM_TOOL\PCB_FOOTPRINTS\Altium_Footprint_Lib.PcbLib; Height: 0.80MM; Library Path: Y:\MIS_DATABASE\Library\ALTIUM_TOOL\SCHEMATICS_PARTS\MS_MOSFET_Library.schlib; Mfr_name: TEXAS INSTRUMENTS; Mistral Part No: 142020120008-R; Package: WSON6; Part_type: ICS\POWER\MOSFET; Project: TI_AM243x LP EVM; RoHS: RoHS; Temperature: -55°C+150°C; Tolerance: NA; Voltage: NA; Wattage: NA; Weight: 8.7mg; Datasheet: Y:\MIS_DATABASE\DATASHEETS\ICS\POWER\CSD16301Q2.PDF
R76 R84-R86 R344-R348 R350 R356 R357 = RESISTOR: RES 2.49K 1/16W 1% 0402; Chkd/date: VASANTHA/270516; Crtd /date: VASANTHA/270516; Custom_Duty: 15%; Customs_HS_Code: 85332119; Distributor_name: DIGIKEY; Distributor_part_number: 311-2.49KLRCT-ND; Footprint Path: Y:\MIS_DATABASE\Library\ALTIUM_TOOL\PCB_FOOTPRINTS\Altium_Footprint_Lib.PcbLib; Height: 0.40MM; Library Path: Y:\MIS_DATABASE\Library\ALTIUM_TOOL\SCHEMATICS_PARTS\MS_DISCRETE_Library.schlib; Mfr_name: YAGEO AMERICA; Mfr_part_number: RC0402FR-072K49L; Mistral Part No: 110016050020-R; Package: 0402; Part_type: RESISTORS\FIXED; Project: TMDXCSKCC; RoHS: RoHS; Temperature: -55°C+155°C; Tolerance: 1%; Voltage: NA; Wattage: 1/16W; Weight: 0.65mg; Datasheet: Y:\MIS_DATABASE\DATASHEETS\RESISTORS\RCXXXXL-SER_MAR18.PDF
R339 = RESISTOR: RES 0E 1/10W 5% 0603; Chkd/date: MANIRAJA/051217; Crtd /date: BAVISH/180211; Custom_Duty: 15%; Customs_HS_Code: 85332119; Distributor_name: DIGIKEY; Distributor_part_number: 311-0.0GRCT-ND; Footprint Path: Y:\MIS_DATABASE\Library\ALTIUM_TOOL\PCB_FOOTPRINTS\Altium_Footprint_Lib.PcbLib; Height: 0.55MM; Library Path: Y:\MIS_DATABASE\Library\ALTIUM_TOOL\SCHEMATICS_PARTS\MS_DISCRETE_Library.schlib; Manufacturer: YAGEO AMERICA; Mfr_name: PANASONIC-ECG; Mfr_part_number: RC0603JR-070RL; Mistral Part No: 110011020013-R; Package: 0603; Part_type: RESISTORS\FIXED; Project: KENNEL; RoHS: RoHS; Temperature: -55°C+155°C; Tolerance: 5%; Voltage: NA; Wattage: 1/10W; Weight: 2mg; Datasheet: Y:\MIS_DATABASE\DATASHEETS\RESISTORS\RCXXXXL-SER_MAR18.PDF
R341 R342 R371 = RESISTOR: RES 220E 1/10W 5% 0402; Chkd/date: VASANTHA/291216; Crtd /date: GEETHA/260406; Custom_Duty: 15%; Customs_HS_Code: 85332119; Distributor_name: DIGIKEY; Distributor_part_number: P220JCT-ND; Footprint Path: Y:\MIS_DATABASE\Library\ALTIUM_TOOL\PCB_FOOTPRINTS\Altium_Footprint_Lib.PcbLib; Height: 0.40MM; Library Path: Y:\MIS_DATABASE\Library\ALTIUM_TOOL\SCHEMATICS_PARTS\MS_DISCRETE_Library.schlib; Mfr_name: PANASONIC-ECG; Mfr_part_number: ERJ-2GEJ221X; Mistral Part No: 110009030506-R; Package: 0402; Part_type: RESISTORS\FIXED; Project: RED EYE; RoHS: RoHS; Temperature: -55°C+155°C; Tolerance: 5%; Voltage: NA; Wattage: 1/10W; Weight: 0.8mg; Datasheet: Y:\MIS_DATABASE\DATASHEETS\RESISTORS\PAN-ERJSER_NOV17.PDF
R349 = RESISTOR: RES 5.76K 1/10W 1% 0402; Chkd/date: MAZHAR/150709; Crtd /date: USMAN/220808; Custom_Duty: 15%; Customs_HS_Code: 85332119; Distributor_name: DIGIKEY; Distributor_part_number: P5.76KLCT-ND; Footprint Path: Y:\MIS_DATABASE\Library\ALTIUM_TOOL\PCB_FOOTPRINTS\Altium_Footprint_Lib.PcbLib; Height: 0.40MM; Library Path: Y:\MIS_DATABASE\Library\ALTIUM_TOOL\SCHEMATICS_PARTS\MS_DISCRETE_Library.schlib; Mfr_name: PANASONIC-ECG; Mfr_part_number: ERJ-2RKF5761X; Mistral Part No: 110009030945-R; Package: 0402; Part_type: RESISTORS\FIXED; Project: CPB; RoHS: RoHS; Temperature: -55°C+155°C; Tolerance: 1%; Voltage: NA; Wattage: 1/10W; Weight: 0.8mg; Datasheet: Y:\MIS_DATABASE\DATASHEETS\RESISTORS\PAN-ERJSER_NOV17.PDF
R352 = RESISTOR: RES 2.2K 1/16W 5% 0402; Chkd/date: VASANTHA/061216; Crtd /date: BAVISH/021210; Custom_Duty: 15%; Customs_HS_Code: 85332119; Distributor_name: DIGIKEY; Distributor_part_number: 311-2.2KJRCT-ND; Footprint Path: Y:\MIS_DATABASE\Library\ALTIUM_TOOL\PCB_FOOTPRINTS\Altium_Footprint_Lib.PcbLib; Height: 0.40MM; Library Path: Y:\MIS_DATABASE\Library\ALTIUM_TOOL\SCHEMATICS_PARTS\MS_DISCRETE_Library.schlib; Mfr_name: YAGEO AMERICA; Mfr_part_number: RC0402JR-072K2L; Mistral Part No: 110010120018-R; Package: 0402; Part_type: RESISTORS\FIXED; Project: TE4; RoHS: RoHS; Temperature: -55°C+155°C; Tolerance: 5%; Voltage: NA; Wattage: 1/16W; Weight: 0.65mg; Datasheet: Y:\MIS_DATABASE\DATASHEETS\RESISTORS\RCXXXXL-SER_MAR18.PDF
R353 R354 = RESISTOR: RES 0E 1/20W 5% 0201; Chkd/date: NAVEED/301214; Crtd /date: MUDDU/120710; Custom_Duty: 15%; Customs_HS_Code: 85332119; Distributor_name: DIGIKEY; Distributor_part_number: 311-0.0NCT-ND; Footprint Path: Y:\MIS_DATABASE\Library\ALTIUM_TOOL\PCB_FOOTPRINTS\Altium_Footprint_Lib.PcbLib; Height: 0.26MM; Library Path: Y:\MIS_DATABASE\Library\ALTIUM_TOOL\SCHEMATICS_PARTS\MS_DISCRETE_Library.schlib; Mfr_name: YAGEO AMERICA; Mfr_part_number: RC0201JR-070RL; Mistral Part No: 110010070067-R; Package: 0201; Part_type: RESISTORS\FIXED; Project: PB_BUGBASE; RoHS: RoHS; Temperature: -55°C+125°C; Tolerance: 5%; Voltage: NA; Wattage: 1/20W; Weight: 0.17mg; Datasheet: Y:\MIS_DATABASE\DATASHEETS\RESISTORS\RCXXXXL-SER_MAR18.PDF
R361 = RESISTOR: RES 10K 1/20W 1% 0201; Chkd/date: VASANTHA/270117; Crtd /date: MANIRAJA/270117; Custom_Duty: 15%; Customs_HS_Code: 85332119; Distributor_name: DIGIKEY; Distributor_part_number: 311-10.0KMCT-ND; Footprint Path: Y:\MIS_DATABASE\Library\ALTIUM_TOOL\PCB_FOOTPRINTS\Altium_Footprint_Lib.PcbLib; Height: 0.26MM; Library Path: Y:\MIS_DATABASE\Library\ALTIUM_TOOL\SCHEMATICS_PARTS\MS_DISCRETE_Library.schlib; Manufacturer: YAGEO AMERICA; Mfr_name: YAGEO AMERICA; Mfr_part_number: RC0201FR-0710KL; Mistral Part No: 110011040018-R; Package: 0201; Part_type: RESISTORS\FIXED; Project: GOLDEN-I LITE; RoHS: RoHS; Temperature: -55°C+125°C; Tolerance: 1%; Voltage: NA; Wattage: 1/20W; Weight: 0.17mg; Datasheet: Y:\MIS_DATABASE\DATASHEETS\RESISTORS\RCXXXXL-SER_MAR18.PDF
R363 = RESISTOR: RES 2.2K 1/20W 5% 0201; Chkd/date: VASANTHA/010117; Crtd /date: MAZHAR/010605; Custom_Duty: 15%; Customs_HS_Code: 85332119; Distributor_name: DIGIKEY; Distributor_part_number: P2.2KAGCT-ND; Footprint Path: Y:\MIS_DATABASE\Library\ALTIUM_TOOL\PCB_FOOTPRINTS\Altium_Footprint_Lib.PcbLib; Height: 0.26MM; Library Path: Y:\MIS_DATABASE\Library\ALTIUM_TOOL\SCHEMATICS_PARTS\MS_DISCRETE_Library.schlib; Mfr_name: PANASONIC-ECG; Mfr_part_number: ERJ-1GEJ222C; Mistral Part No: 110009030427-R; Package: 0201; Part_type: RESISTORS\FIXED; Project: G4SLIM; RoHS: RoHS; Temperature: -55°C+125°C; Tolerance: 5%; Voltage: NA; Wattage: 1/20W; Weight: 0.15mg; Datasheet: Y:\MIS_DATABASE\DATASHEETS\RESISTORS\PAN-ERJXGE-FEB06.PDF
TP22-TP24 TP26 TP27 TP30 TP32 TP100 TP102 = TESTPOINT: TESTPOINT CIR 20 SMD; Chkd/date: SHREESHAIL/171006; Crtd /date: MAZHAR/171006; Custom_Duty: NA; Customs_HS_Code: NA; Distributor_name: NA; Distributor_part_number: NA; Footprint Path: Y:\MIS_DATABASE\Library\ALTIUM_TOOL\PCB_FOOTPRINTS\Altium_Footprint_Lib.PcbLib; Height: NA; Library Path: Y:\MIS_DATABASE\Library\ALTIUM_TOOL\SCHEMATICS_PARTS\MS_DISCRETE_Library.schlib; MECHANICAL 3D STEP FILE: NA; Mfr_name: LOCAL; Mistral Part No: NA; Package: SMD; Project: BT MODULE_CSRBC04; RoHS: NA; Temperature: NA; Tolerance: NA; Voltage: NA; Wattage: NA; Weight: NA; Datasheet: NA
U40 = SN74LVC1G11DCKR_SC70-6: IC SINGLE 3-INPUT POSITIVE-AND GATE SON6; Chkd/date: MANIRAJA/270121; Crtd /date: ALVY/270121; Custom_Duty: 15%; Customs_HS_Code: 85423100; Distributor_name: DIGIKEY; Distributor_part_number: 296-30120-1-ND; Footprint Path: Y:\MIS_DATABASE\Library\ALTIUM_TOOL\PCB_FOOTPRINTS\Altium_Footprint_Lib.PcbLib; Height: 0.60MM; Library Path: Y:\MIS_DATABASE\Library\ALTIUM_TOOL\SCHEMATICS_PARTS\MS_GATE_Library.schlib; Mfr_name: TEXAS INSTRUMENTS; Mistral Part No: 141021010013-R; Package: SON6; Part_type: ICS\DIGITAL\GATES; Project: AM64X_SKEVM; RoHS: RoHS; Temperature: -40°C+125°C; Tolerance: NA; Voltage: NA; Wattage: NA; Weight: 33mg; Datasheet: Y:\MIS_DATABASE\DATASHEETS\ICS\DIGITAL\GATES\SN74LVC1G_NOV16.PDF
U51 = DP83867IRRGZ_VQFN48: IC HIGH IMMUNITY 10/100/1000 Mb/s ETHERNET PHY LAYER TRANSCEIVER VQFN48; Chkd/date: MANIRAJA/110817; Crtd /date: MANIRAJA/110817; Custom_Duty: 15%; Customs_HS_Code: 85423100; Distributor_name: DIGIKEY; Distributor_part_number: DP83867IRRGZT-ND; Height: 1.00MM; Mfr_name: TEXAS INSTRUMENTS; Mistral Part No: 143017080002-R; Package: VQFN48; Part_type: ICS\TELECOM\TRANSCEIVER; Project: TI_SVB_CONTROLLER CARD; RoHS: RoHS; Temperature: -40°C+85°C; Tolerance: NA; Voltage: NA; Wattage: NA; Weight: NA; Datasheet: Y:\MIS_DATABASE\DATASHEETS\ICS\DIGITAL\BUSTRANSCEIVER\DP83867I.PDF
U12 = AM62-EVM_BGA425: IC AM62 SoC MICROPROCESSOR BGA425; Chkd/date: ALVY/110621; Crtd /date: MANIRAJA/110621; Custom_Duty: 15%; Customs_HS_Code: 85423100; Distributor_name: NA; Distributor_part_number: NA; Footprint Path: Y:\MIS_DATABASE\Library\ALTIUM_TOOL\PCB_FOOTPRINTS\Altium_Footprint_Lib.PcbLib; Height: 0.65MM; Library Path: Y:\MIS_DATABASE\Library\ALTIUM_TOOL\SCHEMATICS_PARTS\MS_MICROPROCESSOR_Library.schlib; Mfr_name: TEXAS INSTRUMENTS; Mistral Part No: 141221060001; Package: BGA425; Part_type: ICS\DIGITAL\MICROPROCESSOR; Project: AM62_EVM_BRD; RoHS: NA; Temperature: NA; Tolerance: NA; Voltage: NA; Wattage: NA; Weight: NA; Datasheet: Y:\MIS_DATABASE\DATASHEETS\ICS\DIGITAL\MICROCONTROLLER\AM62-SoC_SVB.PDF

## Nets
DGND: C30.1 C58.2 C61.2 C62.2 C63.2 C67.2 C68.2 C69.2 C70.2 C71.2 C73.2 C76.2 C77.1 C78.2 C84.2 C101.2 C113.1 C148.2 C198.1 C202.2 C203.2 C206.2 C210.2 C301.2 C304.2 C306.2 C307.2 C308.2 C312.1 C315.2 C316.2 C317.2 C318.2 C319.2 C327.2 J6.1(CH-GND) Q7.4(S1) Q7.7(S2) Q8.4(S1) Q8.7(S2) Q9.4(S1) Q9.7(S2) R58.2 R63.2 R84.1 R85.1 R86.1 R111.2 R112.2 R140.2 R190.2 R305.1 R315.2 R339.2 R345.1 R346.1 R348.1 R350.1 R361.2 R388.2 R481.2 U6.3(GND) U9.B3(VSS) U9.C1(VSSQ) U9.E5(VSSQ) U11.2(GND) U26.4(GND) U26.9(EPAD) U33.2(GND) U40.2(GND) U51.49(GND) ; also on sheet 1 3 12 13 14 15 16 17 18 19 20 21 22 26 27 28 29 30 31 32 33 34 35 36 37 38 39 40 41 42 43 44 45
VCC_1V8: C198.2 C202.1 C203.1 C206.1 C210.1 R296.2 R297.2 R303.2 R304.1 R306.2 R307.2 R308.2 R309.2 R310.2 R313.2 R317.2 R318.2 R319.2 U6.5(VCC) U9.B4(VCC) U9.D1(VCCQ) U9.E4(VCCQ) ; also on sheet 14 15 20 21 27 36 39 41 42 44
VCC_3V3_SYS: C30.2 C58.1 C76.1 C84.1 C101.1 C113.2 C148.1 C301.1 C307.1 C315.1 C316.1 C319.1 FL20.1 R76.2 R114.1 R191.2 R192.2 R341.2 R342.1 R344.2 R347.2 R349.1 R351.2 R352.1 R356.2 R357.2 R362.2 R363.1 R371.2 U11.4(V+) U26.8(VCC) U33.4(V+) U40.5(VCC) U51.19(VDDIO) U51.30(VDDIO) U51.41(VDDIO) ; also on sheet 3 12 14 15 16 20 21 22 26 27 28 29 31 32 33 34 35 36 37 38 39 40 41 42 43 44 45
VDD_1V0: C61.1 C62.1 C63.1 C69.1 C70.1 C71.1 C73.1 C306.1 C317.1 C318.1 U51.6(VDD1P0) U51.24(VDD1P0) U51.31(VDD1P0) U51.42(VDD1P0) ; also on sheet 14 26
VDD_2V5: C67.1 C68.1 C77.2 C78.1 C304.1 C308.1 U51.3(VDDA2P5) U51.9(VDDA2P5) ; also on sheet 15 19 26
CPSW1_GPIO_0: J6.14 Q9.1(D1) Q9.2(D2) Q9.5(D3) Q9.6(D4) Q9.8(D5) R371.1
CPSW1_LED_1000: J6.12 Q7.1(D1) Q7.2(D2) Q7.5(D3) Q7.6(D4) Q7.8(D5)
CPSW1_LED_ACT: J6.13 Q8.1(D1) Q8.2(D2) Q8.5(D3) Q8.6(D4) Q8.8(D5) R341.1
CPSW_ETH1_D0N: J6.10(MX0-) U51.2(TD_M_A)
CPSW_ETH1_D0P: J6.9(MX0+) U51.1(TD_P_A)
CPSW_ETH1_D1M: J6.8(MX1-) U51.5(TD_M_B)
CPSW_ETH1_D1P: J6.7(MX1+) U51.4(TD_P_B)
CPSW_ETH1_D2M: J6.6(MX2-) U51.8(TD_M_C)
CPSW_ETH1_D2P: J6.5(MX2+) U51.7(TD_P_C)
CPSW_ETH1_D3M: J6.4(MX3-) U51.11(TD_M_D)
CPSW_ETH1_D3P: J6.3(MX3+) U51.10(TD_P_D)
CPSW_ETH1_GPIO_0: R346.2 R347.1 R354.1 R387.1 TP23.1(TP)
CPSW_ETH1_GPIO_1: R344.1 R345.2 R353.1 TP24.1(TP)
CPSW_ETH1_LED0: TP26.1(TP) U51.47(LED_0)
CPSW_ETH1_LED_1000: R84.2 R335.1 R351.1 TP27.1(TP) U51.46(LED_1)
CPSW_ETH1_LED_ACT: R76.1 R348.2 R383.1 TP22.1(TP) U51.45(LED_2)
CPSW_RGMII1_ETH1_CLK: U51.15(XI) ; also on sheet 27
CPSW_RGMII1_ETH1_CLK_OUT: TP32.1(TP) U51.18(CLK_OUT)
CPSW_RGMII1_ETH1_RBIAS: C312.2 R361.1 U51.12(RBIAS)
CPSW_RGMII1_MDC: R102.2 R362.1 U51.16(MDC)
CPSW_RGMII1_MDIO: R64.2 R363.2 U51.17(MDIO)
CPSW_RGMII1_RD0: R86.2 R357.1 U51.33(RX_D0) ; also on sheet 27
CPSW_RGMII1_RD1: U51.34(RX_D1) ; also on sheet 27
CPSW_RGMII1_RD2: R85.2 R356.1 U51.35(RX_D2) ; also on sheet 27
CPSW_RGMII1_RD3: U51.36(RX_D3) ; also on sheet 27
CPSW_RGMII1_RESETn: R481.1 U40.4(Y) U51.43(RESET_N)
CPSW_RGMII1_RX_CTL: R349.2 R350.2 U51.38(RX_DV/RX_CTRL) ; also on sheet 27
CPSW_RGMII1_RXC: R359.1 ; also on sheet 27
CPSW_RGMII1_TD0: U51.28(TX_D0) ; also on sheet 27
CPSW_RGMII1_TD1: U51.27(TX_D1) ; also on sheet 27
CPSW_RGMII1_TD2: U51.26(TX_D2) ; also on sheet 27
CPSW_RGMII1_TD3: U51.25(TX_D3) ; also on sheet 27
CPSW_RGMII1_TX_CTL: U51.37(TX_EN/TX_CTRL) ; also on sheet 27
CPSW_RGMII1_TXC: U51.29(GTX_CLK) ; also on sheet 27
CPSW_RGMII_INTn: R72.2 R352.2 U51.44(INT/PWDN) ; also on sheet 26
CPSW_RGMII_INTn/PRU_INTn: R72.1 ; also on sheet 34 44
EEPROM_A0: R114.2 U26.1(A0)
EEPROM_A1: R112.1 U26.2(A1)
EEPROM_A2: R111.1 U26.3(A2)
EEPROM_WP: R388.1 U26.7(WP)
ETH1_EARTH: C327.1 J6.15(SH1) J6.16(SH2) R339.1
EXP_GPIO0_14_LT: U12.E24(OSPI0_CSN3) ; also on sheet 36
GPIO_CPSW1_RST: R730.2 ; also on sheet 41
GPIO_OSPI_RSTn: R729.2 U12.G21(OSPI0_CSN1)
OSPI0_CSN0: R39.2 U12.F23(OSPI0_CSN0)
OSPI0_LBCLK: R52.1 R53.1
OSPI_CLK: R312.1 R315.1 U9.B2(CK)
OSPI_CS: R39.1 R304.2 U9.C2(CS#)
OSPI_DQ0: R319.1 RA3.4 U9.D3(DQ0)
OSPI_DQ1: R309.1 RA3.1 U9.D2(DQ1)
OSPI_DQ2: R318.1 RA3.2 U9.C4(DQ2)
OSPI_DQ3: R310.1 RA3.3 U9.D4(DQ3)
OSPI_DQ4: R306.1 RA4.2 U9.D5(DQ4)
OSPI_DQ5: R307.1 RA4.1 U9.E3(DQ5)
OSPI_DQ6: R308.1 RA4.3 U9.E2(DQ6)
OSPI_DQ7: R303.1 RA4.4 U9.E1(DQ7)
OSPI_DQS: R320.1 U9.C3(DS)
OSPI_DQS_SOC: R53.2 R297.1 R305.2 R320.2 U12.J24(OSPI0_DQS)
OSPI_INTn: R317.1 R321.1 U12.H21(OSPI0_CSN2)
OSPI_RSTn: R313.1 U6.4(Y) U9.A4(RESET#)
PORz_OUT: U40.3(B) ; also on sheet 22 26 29 44
RESETSTATz: R189.1 U6.2(B) ; also on sheet 15 21 22 26 29 34 35 39 41 42 43 44
SoC_I2C0_SCL: U26.6(SCL) ; also on sheet 12 15 34 35 39 44
SoC_I2C0_SDA: U26.5(SDA) ; also on sheet 12 15 34 35 39 44
SOC_I2C1_SCL: TP71.1(TP) U11.1(SCL) U33.1(SCL) ; also on sheet 3 16 28 41 42 43 44
SOC_I2C1_SDA: TP72.1(TP) U11.6(SDA) U33.6(SDA) ; also on sheet 3 16 28 41 42 43 44
SoC_OSPI_CLK: R312.2 U12.H24(OSPI0_CLK)
SoC_OSPI_DQ0: RA3.5 U12.E25(OSPI0_D0)
SoC_OSPI_DQ1: RA3.8 U12.G24(OSPI0_D1)
SoC_OSPI_DQ2: RA3.7 U12.F25(OSPI0_D2)
SoC_OSPI_DQ3: RA3.6 U12.F24(OSPI0_D3)
SoC_OSPI_DQ4: RA4.7 U12.J23(OSPI0_D4)
SoC_OSPI_DQ5: RA4.8 U12.J25(OSPI0_D5)
SoC_OSPI_DQ6: RA4.6 U12.H25(OSPI0_D6)
SoC_OSPI_DQ7: RA4.5 U12.J22(OSPI0_D7)
SOC_RGMII_MDC: R102.1 ; also on sheet 26 34
SOC_RGMII_MDIO: R64.1 ; also on sheet 26 34
TMP1_ADD0: R58.1 U11.5(ADD0)
TMP1_ADD1: R63.1 U11.3(ADD1)
TMP2_ADD1: R140.1 U33.3(ADD1)
N16956470: R52.2 U12.G25(OSPI0_LBCLKO)
N16960510: R321.2 U9.A5(INT#)
N17110597: TP100.1(TP) U51.13(VDDA1P8)
N17133547: FL20.2 J6.2(VCC)
N17137240: J6.11 R342.2
N17167245: R359.2 U51.32(RX_CLK)
N17269599: R189.2 R192.1 U40.6(C)
N17269609: R190.1 R191.1 R730.1 U40.1(A)
N17653582: Q7.3(G) R335.2
N17796705: Q8.3(G) R383.2
N17796716: Q9.3(G) R387.2
N18576337: R354.2 U51.39(GPIO_0)
N18576340: R353.2 U51.40(GPIO_1)
N20273833: TP30.1(TP) U51.48(VDDA1P8)
N20274021: TP102.1(TP) U51.14(XO)
N22104448: R296.1 R729.1 U6.1(A)

Not connected (* = marked no-connect by the designer): U9 A2(DNU1)* A3(DNU2)* B1(DNU3)* B5(DNU4)* C5(DNU5)*; U33 5(ADD0)*; U51 20(JTAG_CLK)* 21(JTAG_TDO)* 22(JTAG_TMS)* 23(JTAG_TDI)*

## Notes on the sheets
sheet 23
- D-Note:
  Refer Custom Board Design and Simulation Guidelines for
  Processor High Speed Parallel Interfaces
  https://www.ti.com/lit/pdf/sdaa087
- D-Note:
  0R resistors are used for configuring QSPI0 or OSPI0 interface.
  This is optional for custom board design.
- OSPI  FLASH
- R-Note:
  SoC IO buffers are off during reset and after reset.
  A pullup is recommended to hold the attached
  device IOs in a known state (does not float).
  Usage of pullups are attached device dependent.
- CAD Note:
  Place RA3 & RA4 closer to the attached Memory Device
- SOC OSPI INTERFACE
- D-Note:
  Connecting OSPI0 interface
  to multiple devices is not
  recommended or supported.
- D-Note:
  0E provision on OSPI0_CLK has
  been provided for control of possible
  signal reflections
- C
- V
- V
- C
- D-Note:
  Pullup is DNI
- CAD Note:
  Place R53 & R320 as tripad to minimize stub
- CAD Note:
  Place R52 close to the SOC
  LBCLK0 pin with minimum trace length
- D-Note:
  For QSPI configuration, remove 0E resistors from the following:
  1. OSPI_DQ4 to OSPI_DQ7 nets (RA4)
  2. OSPI_INTn pullup (R317)
  OSPI NOR Flash can be replaced with a footprint compatible
  OSPI NAND Flash (Mfr Part# W35N01JWTBAG).
- C
- D-Note:
  Choice of QSPI memory device:
  For improved performance, it is recommended to
  select a QSPI memory device with an external reset
  input pin. The reset input pin is recommended to be
  controlled using SoC reset status output or an
  ANDing logic as implemented in the starter kit.
- D-Note:
  External loopback clock series resistors are DNI when DQS is connected.
- R-Note:
  DQS pull-down is enabled.
  Place pull-down closer to the SoC.
- OSPI  FLASH RESET
- D-Note:
  The GPIO reset option makes it possible for the
  software to reset the attached device (eMMC or
  OSPI or SD card or OLDI or EPHY) without
  resetting the entire processor, if there is a
  case where the peripheral becomes unresponsive.
- D-Note:
  You could eliminate the GPIO option
  and only use the reset output
  (warm or cold), where the software
  forces a warm reset, if the peripheral
  becomes unresponsive. However,
  this will reset the entire device, rather
  than trying to recover the specific
  peripheral without resetting the
  entire device.
- D-Note:
  In case ANDing logic is not used and the processor
  Main domain warm reset status output (RESETSTATz)
  is used to reset the attached device, ensure the IO voltage
  level of the attached device matches the RESETSTATz IO
  voltage level. A level translator is recommended to match
  the IO voltage level. A resistor divider can be used
  alternatively, provided optimum impedance value of the
  resistor divider is selected. In case the value is too high, the
  rise/fall time of the OSPI0 reset input can be slow and
  introduce too much delay. In case the value is too low, it will
  cause the AM62x to source too much steady-state current
  during normal operation.
- D-Note:
  ANDing logic additionally performs level translation.
  Verify the reset IO level compatibility before optimizing
  the reset ANDing logic. IO level mismatch can cause
  residual voltage (supply leakage) and affect PMIC/SoC
  operation.
sheet 24
- BOARD ID EEPROM
- I2C ADDRESS: 0X51
- DIGITAL TEMPERATURE SENSORS
- I2C ADDRESS: 0x48
- I2C ADDRESS: 0x49
- CAD Note:
  Place the temperature sensor closer to the SoC.
- CAD Note:
  Place the temperature sensor closer to the SoC.
- Silk: SOC_I2C1
sheet 25
- D-Note:
  The caps and values used are as per the EPHY
  data sheet recommendations.
- CPSW3G RGMII 1 - ETHERNET PHY
- D-Note:
  Ok to use 0402 package for 1uF cap to
  match the 10uF bulk cap package size
- D-Note:
  Refer to DP83867ERGZ-R-EVM when using Discrete LAN
  Transformer Module and RJ45 connector.
- R-Note:
  Ferrite is DNI.
- D-Note:
  Refer Custom Board Design and Simulation Guidelines for
  Processor High Speed Parallel Interfaces
  https://www.ti.com/lit/pdf/sdaa087
- D-Note:
  Verify the power sequence requirements for
  Two-Supply Configuration and Three-Supply
  Configuration.
- RJ45 CONNECTOR WITH
  INTEGRATED MAGNETICS
- 100E
- 100E
- 100E
- D-Note:
  Provide provision for series resistor
  based on EPHY for RDX signals near
  to the EPHY.
- 100E
- D-Note:
  Allowed amplitude for XI clock input
  is 1.8V irrespective of the IO supply
  used. Use a capacitor divider when
  the clock applied is 3.3V.
- D-Note:
  Refer to the EPHY EVM for JTAG connections.
- C.
- D-Note:
  RBIAS resistor value has
  been reduced from 11K
  and a parallel capacitor
  has been added to improve
  Ethernet compliance
  testing performance
- D-Note:
  ANDing logic could be optimized to a 2-input AND gate. Use RESETSTATz (or
  PORz_OUT) and the SoC IO as inputs to the ANDing logic.
- Silk: CPSW PHY-1
- Note:
  Pull-up is enabled for GPIO input.
  RESETSTATz series resistor is DNI.
- D-Note:
  ANDing logic additionally performs level translation. Verify
  the reset IO level compatibility before optimizing the reset
  ANDing logic. IO level mismatch can cause residual voltage
  (supply leakage) and affect PMIC/SoC operation.
- PHY ADDRESS = 00000
- Auto-negotiation Enabled
- 10/100/1000 advertised, Auto-MDI-X
- Tx Clock Skew = 0ns
- Rx Clock Skew = 2ns
